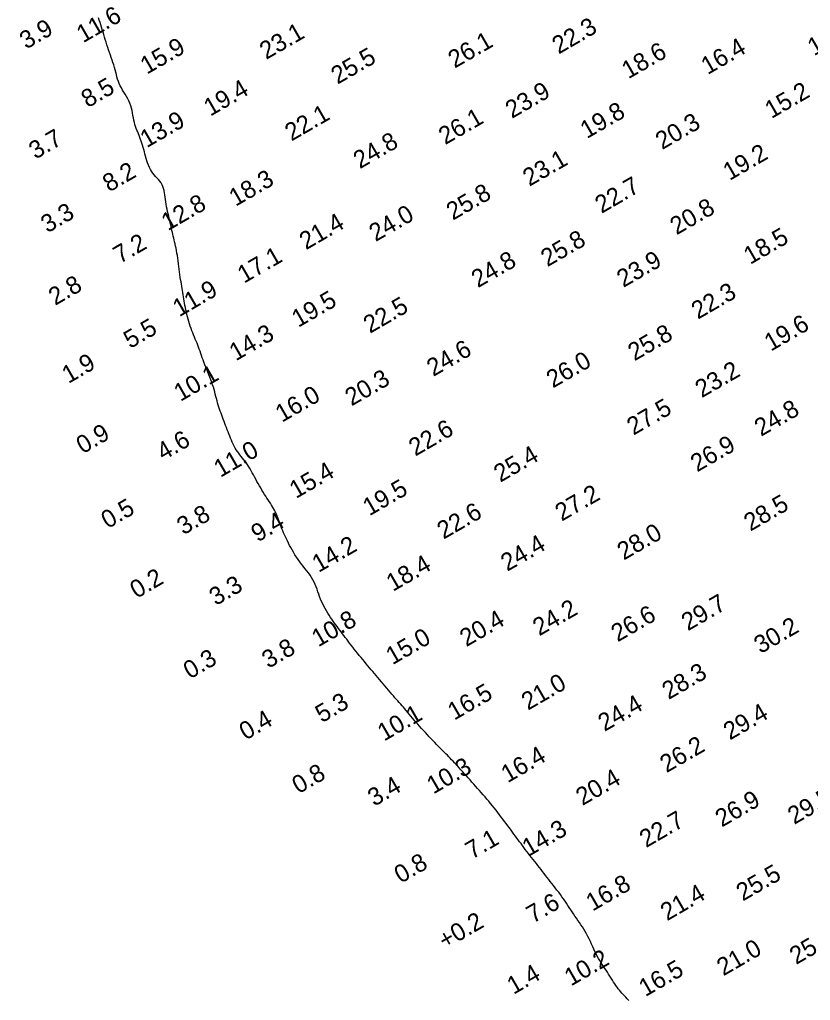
# Model space of a CAD drawing. Extents: x 3024098 to 3056816, y 418252 to 509144.
# Drawn here: x 3026905.5 to 3027129.2, y 420042.8 to 420320.3 of the extents above; entities that cross this region are included whole.
import ezdxf

# ---------------------------------------------------------------- set-up
doc = ezdxf.new("R2010")
doc.units = 0
doc.layers.add('V-CHAN-CONT-EL10', color=7, linetype='Continuous')
doc.layers.add('V-TOPO-SOUN-0911', color=7, linetype='Continuous')

msp = doc.modelspace()

# ---------------------------------------------------------------- linework, layer by layer
at = {"layer": 'V-CHAN-CONT-EL10'}
msp.add_lwpolyline([(3027077.83, 420042.71), (3027077.4, 420043.17), (3027076.99, 420043.62), (3027076.6, 420044.04), (3027076.23, 420044.44), (3027075.88, 420044.84), (3027075.54, 420045.24), (3027075.21, 420045.64), (3027074.88, 420046.06), (3027074.56, 420046.49), (3027074.23, 420046.94), (3027073.9, 420047.43), (3027073.56, 420047.94), (3027073.21, 420048.47), (3027072.86, 420049.02), (3027072.51, 420049.58), (3027072.15, 420050.14), (3027071.79, 420050.71), (3027071.43, 420051.27), (3027071.07, 420051.82), (3027070.71, 420052.37), (3027070.35, 420052.92), (3027069.99, 420053.48), (3027069.63, 420054.05), (3027069.29, 420054.64), (3027068.94, 420055.25), (3027068.61, 420055.88), (3027068.28, 420056.55), (3027067.96, 420057.24), (3027067.64, 420057.95), (3027067.32, 420058.67), (3027066.99, 420059.4), (3027066.65, 420060.13), (3027066.3, 420060.84), (3027065.93, 420061.55), (3027065.55, 420062.23), (3027065.14, 420062.89), (3027064.73, 420063.54), (3027064.3, 420064.17), (3027063.87, 420064.79), (3027063.44, 420065.4), (3027063.02, 420066), (3027062.6, 420066.6), (3027062.2, 420067.21), (3027061.8, 420067.81), (3027061.41, 420068.41), (3027061.02, 420069.01), (3027060.62, 420069.62), (3027060.22, 420070.23), (3027059.81, 420070.84), (3027059.39, 420071.46), (3027058.94, 420072.09), (3027058.49, 420072.71), (3027058.02, 420073.34), (3027057.54, 420073.97), (3027057.07, 420074.6), (3027056.59, 420075.22), (3027056.12, 420075.82), (3027055.65, 420076.42), (3027055.2, 420077), (3027054.76, 420077.57), (3027054.32, 420078.13), (3027053.89, 420078.69), (3027053.46, 420079.24), (3027053.03, 420079.79), (3027052.6, 420080.35), (3027052.16, 420080.91), (3027051.71, 420081.48), (3027051.26, 420082.05), (3027050.81, 420082.63), (3027050.35, 420083.21), (3027049.9, 420083.79), (3027049.45, 420084.36), (3027049.01, 420084.92), (3027048.58, 420085.48), (3027048.17, 420086.03), (3027047.76, 420086.57), (3027047.36, 420087.1), (3027046.96, 420087.63), (3027046.57, 420088.16), (3027046.18, 420088.7), (3027045.78, 420089.24), (3027045.37, 420089.8), (3027044.95, 420090.36), (3027044.53, 420090.95), (3027044.09, 420091.54), (3027043.65, 420092.15), (3027043.19, 420092.76), (3027042.73, 420093.38), (3027042.26, 420094.01), (3027041.78, 420094.64), (3027041.29, 420095.28), (3027040.8, 420095.91), (3027040.29, 420096.55), (3027039.79, 420097.19), (3027039.27, 420097.83), (3027038.75, 420098.46), (3027038.23, 420099.09), (3027037.71, 420099.71), (3027037.18, 420100.33), (3027036.65, 420100.94), (3027036.12, 420101.55), (3027035.58, 420102.15), (3027035.05, 420102.75), (3027034.52, 420103.35), (3027033.99, 420103.94), (3027033.46, 420104.54), (3027032.93, 420105.13), (3027032.4, 420105.72), (3027031.89, 420106.31), (3027031.37, 420106.88), (3027030.87, 420107.45), (3027030.38, 420107.99), (3027029.9, 420108.52), (3027029.44, 420109.03), (3027029, 420109.51), (3027028.57, 420109.98), (3027028.15, 420110.42), (3027027.74, 420110.85), (3027027.33, 420111.27), (3027026.93, 420111.69), (3027026.53, 420112.1), (3027026.12, 420112.52), (3027025.71, 420112.93), (3027025.28, 420113.36), (3027024.85, 420113.79), (3027024.41, 420114.24), (3027023.95, 420114.7), (3027023.48, 420115.18), (3027022.99, 420115.68), (3027022.48, 420116.21), (3027021.96, 420116.75), (3027021.42, 420117.32), (3027020.87, 420117.91), (3027020.32, 420118.51), (3027019.76, 420119.11), (3027019.21, 420119.72), (3027018.67, 420120.32), (3027018.14, 420120.92), (3027017.63, 420121.51), (3027017.14, 420122.08), (3027016.67, 420122.65), (3027016.21, 420123.2), (3027015.76, 420123.73), (3027015.33, 420124.25), (3027014.91, 420124.75), (3027014.5, 420125.23), (3027014.1, 420125.69), (3027013.71, 420126.14), (3027013.32, 420126.58), (3027012.92, 420127.02), (3027012.53, 420127.47), (3027012.12, 420127.92), (3027011.7, 420128.4), (3027011.26, 420128.9), (3027010.81, 420129.42), (3027010.34, 420129.98), (3027009.85, 420130.55), (3027009.36, 420131.13), (3027008.86, 420131.73), (3027008.35, 420132.32), (3027007.85, 420132.92), (3027007.36, 420133.51), (3027006.87, 420134.08), (3027006.39, 420134.65), (3027005.91, 420135.21), (3027005.44, 420135.77), (3027004.97, 420136.32), (3027004.5, 420136.88), (3027004.02, 420137.44), (3027003.54, 420138.02), (3027003.06, 420138.6), (3027002.58, 420139.18), (3027002.09, 420139.78), (3027001.61, 420140.37), (3027001.13, 420140.97), (3027000.66, 420141.56), (3027000.19, 420142.15), (3026999.74, 420142.73), (3026999.3, 420143.29), (3026998.87, 420143.85), (3026998.45, 420144.4), (3026998.04, 420144.94), (3026997.64, 420145.47), (3026997.24, 420145.99), (3026996.85, 420146.5), (3026996.46, 420147.01), (3026996.08, 420147.51), (3026995.7, 420148), (3026995.32, 420148.5), (3026994.94, 420149), (3026994.56, 420149.51), (3026994.18, 420150.04), (3026993.8, 420150.58), (3026993.42, 420151.14), (3026993.04, 420151.72), (3026992.67, 420152.33), (3026992.29, 420152.96), (3026991.93, 420153.6), (3026991.58, 420154.26), (3026991.25, 420154.93), (3026990.94, 420155.61), (3026990.65, 420156.3), (3026990.38, 420157), (3026990.13, 420157.69), (3026989.89, 420158.39), (3026989.64, 420159.08), (3026989.39, 420159.77), (3026989.11, 420160.46), (3026988.81, 420161.13), (3026988.47, 420161.79), (3026988.08, 420162.44), (3026987.66, 420163.08), (3026987.2, 420163.71), (3026986.72, 420164.34), (3026986.23, 420164.96), (3026985.73, 420165.59), (3026985.24, 420166.23), (3026984.75, 420166.87), (3026984.29, 420167.53), (3026983.84, 420168.2), (3026983.41, 420168.87), (3026983, 420169.54), (3026982.61, 420170.21), (3026982.24, 420170.87), (3026981.9, 420171.51), (3026981.57, 420172.14), (3026981.26, 420172.74), (3026980.97, 420173.33), (3026980.7, 420173.91), (3026980.44, 420174.48), (3026980.2, 420175.04), (3026979.96, 420175.6), (3026979.73, 420176.17), (3026979.5, 420176.75), (3026979.28, 420177.34), (3026979.06, 420177.94), (3026978.84, 420178.55), (3026978.61, 420179.15), (3026978.38, 420179.74), (3026978.14, 420180.32), (3026977.9, 420180.89), (3026977.64, 420181.43), (3026977.36, 420181.95), (3026977.08, 420182.44), (3026976.78, 420182.92), (3026976.47, 420183.4), (3026976.15, 420183.87), (3026975.82, 420184.36), (3026975.49, 420184.86), (3026975.14, 420185.38), (3026974.78, 420185.94), (3026974.42, 420186.52), (3026974.06, 420187.12), (3026973.7, 420187.74), (3026973.33, 420188.36), (3026972.98, 420188.99), (3026972.63, 420189.62), (3026972.29, 420190.25), (3026971.96, 420190.86), (3026971.64, 420191.46), (3026971.33, 420192.04), (3026971.02, 420192.61), (3026970.7, 420193.17), (3026970.38, 420193.71), (3026970.05, 420194.23), (3026969.71, 420194.74), (3026969.35, 420195.23), (3026968.98, 420195.7), (3026968.6, 420196.17), (3026968.22, 420196.63), (3026967.85, 420197.09), (3026967.48, 420197.56), (3026967.12, 420198.04), (3026966.79, 420198.53), (3026966.48, 420199.04), (3026966.19, 420199.58), (3026965.91, 420200.13), (3026965.66, 420200.69), (3026965.41, 420201.26), (3026965.17, 420201.84), (3026964.94, 420202.43), (3026964.71, 420203.03), (3026964.48, 420203.62), (3026964.25, 420204.22), (3026964.02, 420204.82), (3026963.79, 420205.42), (3026963.57, 420206.01), (3026963.34, 420206.6), (3026963.12, 420207.19), (3026962.91, 420207.77), (3026962.69, 420208.35), (3026962.49, 420208.92), (3026962.28, 420209.49), (3026962.09, 420210.07), (3026961.89, 420210.64), (3026961.71, 420211.22), (3026961.53, 420211.81), (3026961.35, 420212.41), (3026961.19, 420213.02), (3026961.02, 420213.64), (3026960.86, 420214.28), (3026960.69, 420214.93), (3026960.51, 420215.59), (3026960.32, 420216.26), (3026960.11, 420216.95), (3026959.88, 420217.65), (3026959.63, 420218.35), (3026959.36, 420219.07), (3026959.07, 420219.79), (3026958.78, 420220.52), (3026958.49, 420221.23), (3026958.2, 420221.94), (3026957.92, 420222.63), (3026957.65, 420223.31), (3026957.4, 420223.97), (3026957.17, 420224.6), (3026956.96, 420225.23), (3026956.75, 420225.83), (3026956.54, 420226.42), (3026956.34, 420227.01), (3026956.13, 420227.59), (3026955.91, 420228.16), (3026955.69, 420228.73), (3026955.45, 420229.3), (3026955.21, 420229.87), (3026954.97, 420230.45), (3026954.72, 420231.03), (3026954.48, 420231.63), (3026954.24, 420232.24), (3026954, 420232.86), (3026953.78, 420233.5), (3026953.57, 420234.15), (3026953.37, 420234.82), (3026953.17, 420235.48), (3026952.99, 420236.15), (3026952.83, 420236.82), (3026952.67, 420237.48), (3026952.53, 420238.13), (3026952.41, 420238.77), (3026952.29, 420239.4), (3026952.19, 420240.02), (3026952.09, 420240.62), (3026952, 420241.23), (3026951.9, 420241.82), (3026951.81, 420242.42), (3026951.71, 420243.01), (3026951.61, 420243.61), (3026951.5, 420244.21), (3026951.4, 420244.82), (3026951.28, 420245.45), (3026951.17, 420246.09), (3026951.06, 420246.74), (3026950.95, 420247.43), (3026950.84, 420248.14), (3026950.74, 420248.88), (3026950.64, 420249.65), (3026950.54, 420250.42), (3026950.44, 420251.21), (3026950.35, 420251.99), (3026950.24, 420252.76), (3026950.13, 420253.51), (3026950.02, 420254.22), (3026949.9, 420254.91), (3026949.77, 420255.56), (3026949.64, 420256.18), (3026949.5, 420256.78), (3026949.36, 420257.35), (3026949.23, 420257.91), (3026949.09, 420258.45), (3026948.97, 420258.99), (3026948.84, 420259.52), (3026948.72, 420260.05), (3026948.61, 420260.59), (3026948.49, 420261.13), (3026948.37, 420261.67), (3026948.25, 420262.24), (3026948.12, 420262.81), (3026947.98, 420263.41), (3026947.84, 420264.03), (3026947.68, 420264.67), (3026947.53, 420265.32), (3026947.37, 420265.98), (3026947.22, 420266.66), (3026947.08, 420267.34), (3026946.95, 420268.01), (3026946.84, 420268.69), (3026946.75, 420269.36), (3026946.66, 420270.02), (3026946.58, 420270.66), (3026946.48, 420271.29), (3026946.37, 420271.9), (3026946.22, 420272.48), (3026946.04, 420273.04), (3026945.8, 420273.56), (3026945.51, 420274.06), (3026945.17, 420274.53), (3026944.79, 420274.99), (3026944.39, 420275.43), (3026943.98, 420275.89), (3026943.57, 420276.35), (3026943.18, 420276.83), (3026942.81, 420277.34), (3026942.49, 420277.89), (3026942.2, 420278.47), (3026941.94, 420279.07), (3026941.71, 420279.7), (3026941.5, 420280.33), (3026941.31, 420280.98), (3026941.13, 420281.62), (3026940.96, 420282.26), (3026940.79, 420282.89), (3026940.62, 420283.51), (3026940.46, 420284.11), (3026940.29, 420284.7), (3026940.11, 420285.28), (3026939.93, 420285.84), (3026939.74, 420286.39), (3026939.55, 420286.92), (3026939.34, 420287.44), (3026939.13, 420287.96), (3026938.92, 420288.47), (3026938.7, 420288.98), (3026938.5, 420289.5), (3026938.3, 420290.04), (3026938.12, 420290.61), (3026937.96, 420291.2), (3026937.82, 420291.83), (3026937.69, 420292.48), (3026937.57, 420293.16), (3026937.44, 420293.85), (3026937.3, 420294.54), (3026937.14, 420295.24), (3026936.94, 420295.92), (3026936.71, 420296.6), (3026936.42, 420297.25), (3026936.09, 420297.89), (3026935.74, 420298.51), (3026935.37, 420299.13), (3026935, 420299.73), (3026934.64, 420300.34), (3026934.29, 420300.95), (3026933.98, 420301.56), (3026933.7, 420302.17), (3026933.46, 420302.8), (3026933.24, 420303.44), (3026933.05, 420304.08), (3026932.87, 420304.74), (3026932.69, 420305.4), (3026932.51, 420306.07), (3026932.32, 420306.75), (3026932.12, 420307.43), (3026931.9, 420308.13), (3026931.66, 420308.83), (3026931.42, 420309.54), (3026931.18, 420310.25), (3026930.93, 420310.97), (3026930.68, 420311.7), (3026930.44, 420312.42), (3026930.2, 420313.15), (3026929.98, 420313.88), (3026929.75, 420314.61), (3026929.53, 420315.33), (3026929.32, 420316.05), (3026929.1, 420316.76), (3026928.89, 420317.46), (3026928.68, 420318.15), (3026928.47, 420318.82), (3026928.25, 420319.48), (3026928.04, 420320.13), (3026927.83, 420320.78)], dxfattribs=at)

# ---------------------------------------------------------------- texts
at = {"layer": 'V-TOPO-SOUN-0911'}
for s, p in [('11.6 ', (3026923.46, 420313.56)), ('3.9', (3026907.35, 420311.76)), ('22.3 ', (3027058.01, 420310.37)), ('12.9 ', (3027130.28, 420309.88)), ('23.1 ', (3026975.25, 420308.84)), ('15.9 ', (3026941.5, 420304.66)), ('26.1 ', (3027028.59, 420306.38)), ('16.4 ', (3027100.16, 420304.56)), ('25.5 ', (3026995.46, 420301.84)), ('18.6 ', (3027077.72, 420303.36)), ('8.5', (3026924.76, 420295.19)), ('19.4 ', (3026959.45, 420292.79)), ('23.9 ', (3027044.78, 420292.16)), ('15.2 ', (3027118.21, 420292.13)), ('22.1 ', (3026982.4, 420285.75)), ('19.8 ', (3027065.98, 420286.45)), ('13.9 ', (3026941.44, 420283.86)), ('26.1 ', (3027025.9, 420284.73)), ('20.3 ', (3027087.27, 420283.34)), ('3.7', (3026909.97, 420280.62)), ('24.8 ', (3027001.77, 420277.92)), ('19.2 ', (3027106.37, 420274.61)), ('23.1 ', (3027049.72, 420272.95)), ('8.2', (3026930.84, 420271.34)), ('18.3 ', (3026966.6, 420267.29)), ('22.7 ', (3027070.14, 420265.29)), ('25.8 ', (3027028.08, 420263.36)), ('12.8 ', (3026947.44, 420260.37)), ('3.3', (3026913.35, 420259.76)), ('24.0 ', (3027006.22, 420257.32)), ('20.8 ', (3027091.37, 420259.22)), ('21.4 ', (3026986.52, 420254.99)), ('7.2', (3026933.86, 420251.09)), ('25.8 ', (3027054.82, 420250.2)), ('18.5 ', (3027112.2, 420250.86)), ('17.1 ', (3026968.98, 420245.52)), ('24.8 ', (3027035.17, 420244.26)), ('23.9 ', (3027076.31, 420244.33)), ('2.8', (3026915.55, 420239.25)), ('11.9 ', (3026950.66, 420236.03)), ('22.3 ', (3027097.41, 420235.34)), ('19.5 ', (3026984.34, 420233.04)), ('22.5 ', (3027004.62, 420231.34)), ('19.6 ', (3027118.04, 420226.29)), ('5.5', (3026936.77, 420227.05)), ('14.3 ', (3026966.67, 420223.56)), ('25.8 ', (3027079.46, 420223.56)), ('24.6 ', (3027022.54, 420219.14)), ('26.0 ', (3027056.38, 420215.88)), ('1.9', (3026919.32, 420217.17)), ('23.2 ', (3027098.49, 420213.13)), ('10.1 ', (3026951, 420212.09)), ('20.3 ', (3026999.41, 420210.8)), ('16.0 ', (3026979.71, 420206.17)), ('27.5 ', (3027079.16, 420202.53)), ('24.8 ', (3027115.26, 420202.2)), ('22.6 ', (3027017.45, 420196.6)), ('0.9', (3026923.36, 420197.26)), ('4.6', (3026946.13, 420195.36)), ('11.0 ', (3026962.29, 420190.59)), ('26.9 ', (3027097.18, 420192.13)), ('25.4 ', (3027041.5, 420189.21)), ('15.4 ', (3026983.69, 420184.62)), ('19.5 ', (3027004.45, 420179.7)), ('27.2 ', (3027058.86, 420178.19)), ('0.5', (3026930.4, 420176.09)), ('28.5 ', (3027112.26, 420175.37)), ('3.8', (3026951.84, 420174.32)), ('22.6 ', (3027025.46, 420173.11)), ('9.4', (3026972.83, 420172.29)), ('28.0 ', (3027076.43, 420167.19)), ('14.2 ', (3026990.09, 420163.69)), ('24.4 ', (3027043.47, 420164.01)), ('18.4 ', (3027011.09, 420158.31)), ('0.2', (3026938.58, 420156.34)), ('3.3', (3026960.99, 420154.31)), ('29.7 ', (3027094.59, 420147.18)), ('24.2 ', (3027052.53, 420145.74)), ('26.6 ', (3027074.7, 420144.04)), ('10.8 ', (3026989.99, 420142.62)), ('20.4 ', (3027031.89, 420142.69)), ('30.2 ', (3027115.13, 420140.72)), ('15.0 ', (3027010.98, 420137.57)), ('3.8', (3026975.89, 420136.53)), ('0.3', (3026953.67, 420133.54)), ('28.3 ', (3027089.11, 420127.73)), ('21.0 ', (3027049.33, 420124.71)), ('16.5 ', (3027028.47, 420121.89)), ('5.3', (3026991.01, 420121.17)), ('24.4 ', (3027071, 420118.71)), ('10.1 ', (3027008.61, 420115.96)), ('29.4 ', (3027106.46, 420116.28)), ('0.4', (3026969.46, 420116.25)), ('26.2 ', (3027088.52, 420107.03)), ('16.4 ', (3027043.57, 420104.17)), ('0.8', (3026984.42, 420101.06)), ('10.3 ', (3027022.54, 420100.99)), ('20.4 ', (3027064.73, 420097.74)), ('3.4', (3027005.84, 420097.52)), ('26.9 ', (3027104.17, 420091.64)), ('29.5 ', (3027124.66, 420092.39)), ('22.7 ', (3027082.74, 420085.83)), ('14.3 ', (3027049.54, 420083.37)), ('7.1', (3027033.48, 420082.57)), ('0.8', (3027013.32, 420075.73)), ('25.5 ', (3027110.1, 420070.71)), ('16.8 ', (3027067.59, 420067.85)), ('7.6', (3027050.72, 420064.45)), ('21.4 ', (3027088.68, 420065.13)), ('+0.2 ', (3027025.82, 420057.12)), ('25.4 ', (3027125.2, 420052.76)), ('21.0 ', (3027104.61, 420049.54)), ('10.2 ', (3027061.48, 420046.66)), ('16.5 ', (3027082.54, 420043.67)), ('1.4', (3027045.24, 420044.3))]:
    msp.add_text(s, height=5, rotation=30, dxfattribs=at).set_placement(p)

doc.saveas('drawing.dxf')
